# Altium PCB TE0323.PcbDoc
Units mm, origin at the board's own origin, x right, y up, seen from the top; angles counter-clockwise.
Board outline 115 x 70 mm, 4 copper layers (L 01 (Top), L 02, L 03, L 04 (Bot)), stack 1.564 mm thick; 54 components, 144 nets, 448 pads, 152 vias.
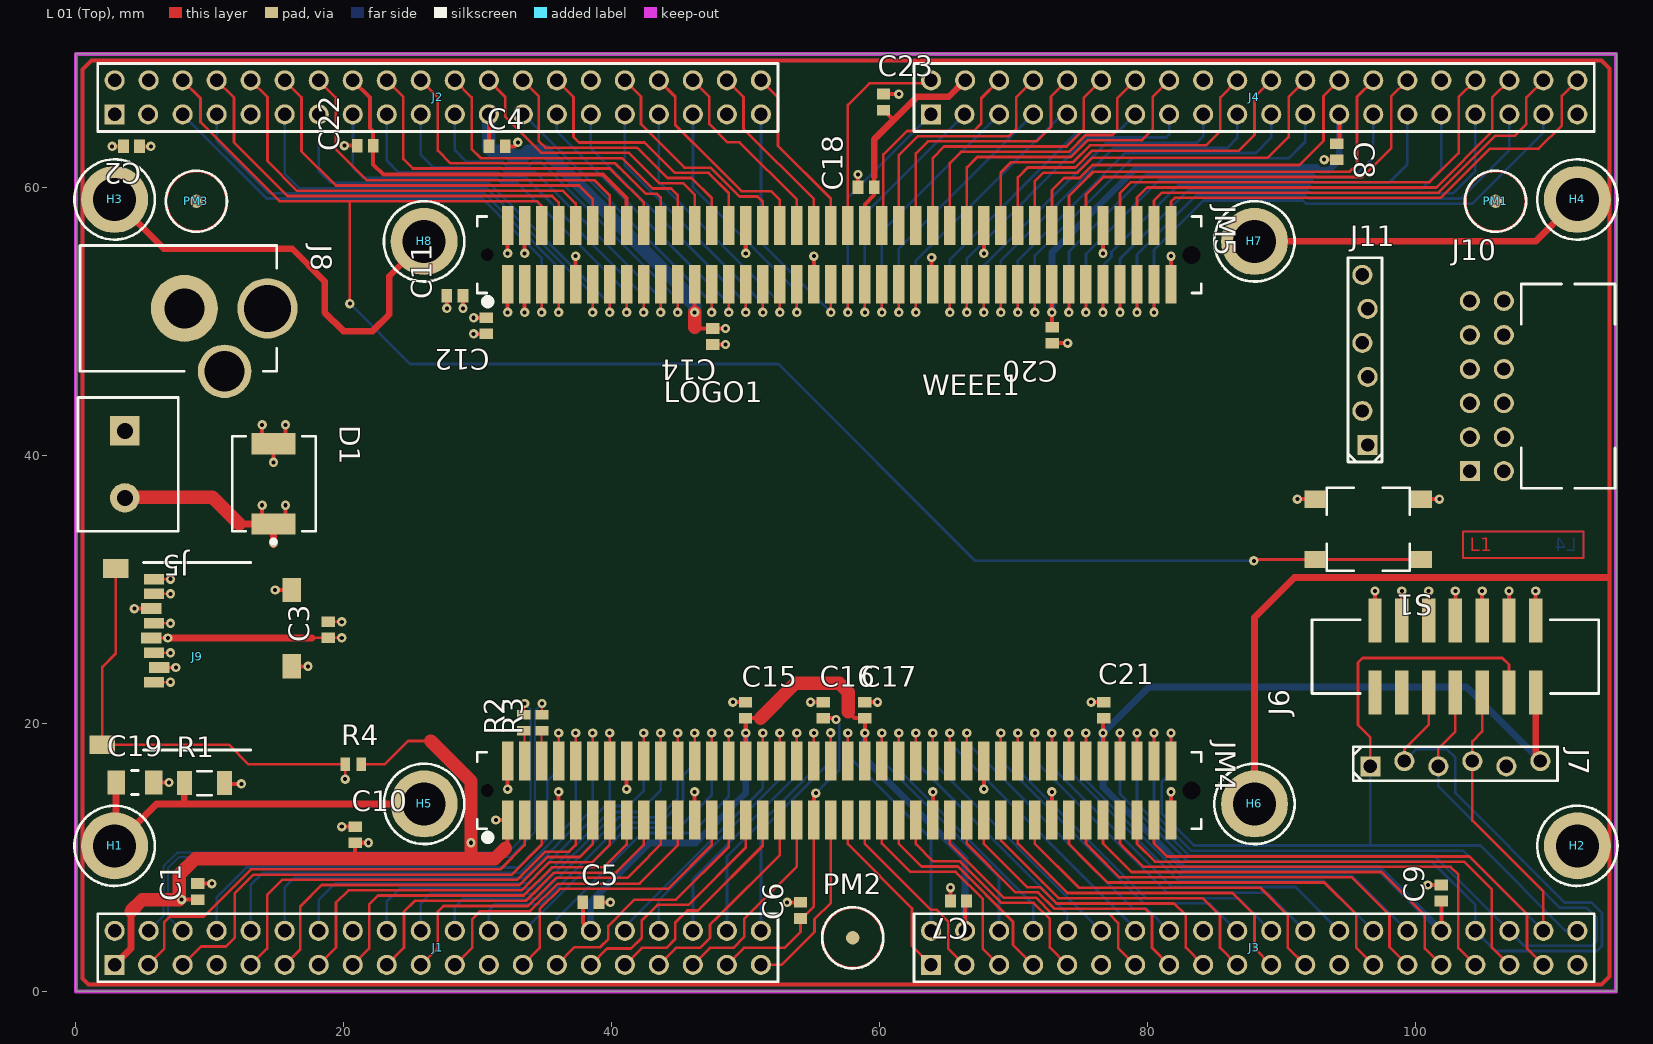
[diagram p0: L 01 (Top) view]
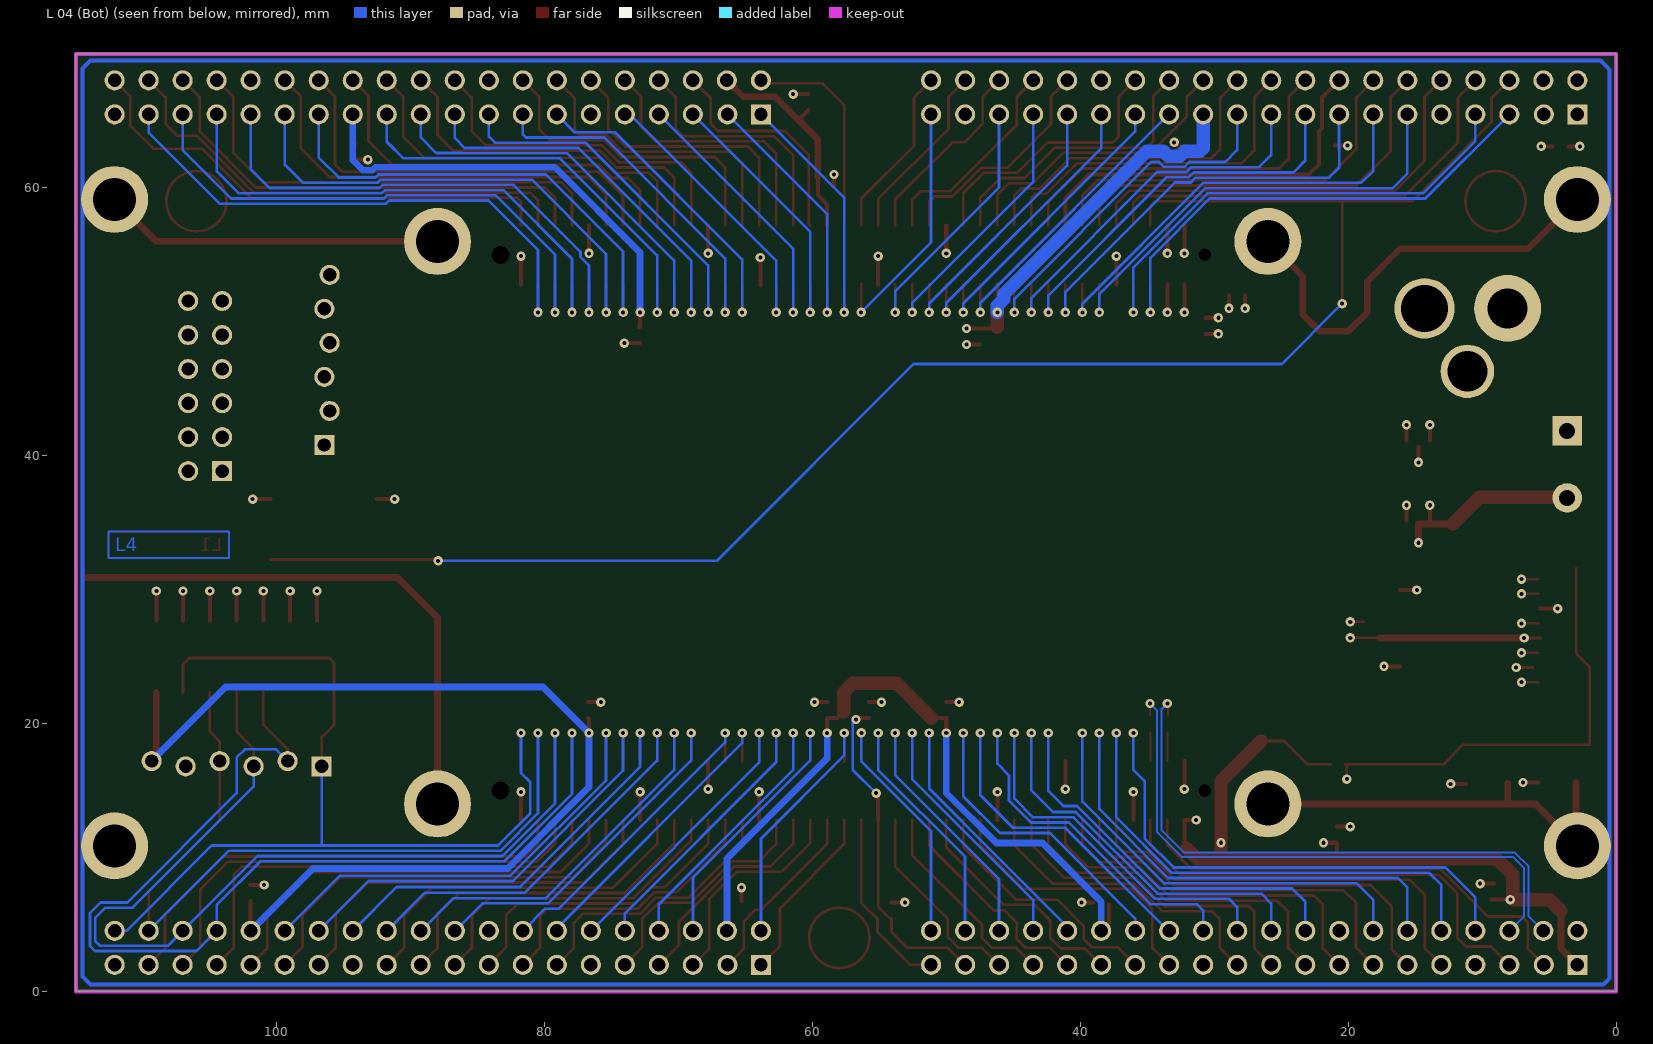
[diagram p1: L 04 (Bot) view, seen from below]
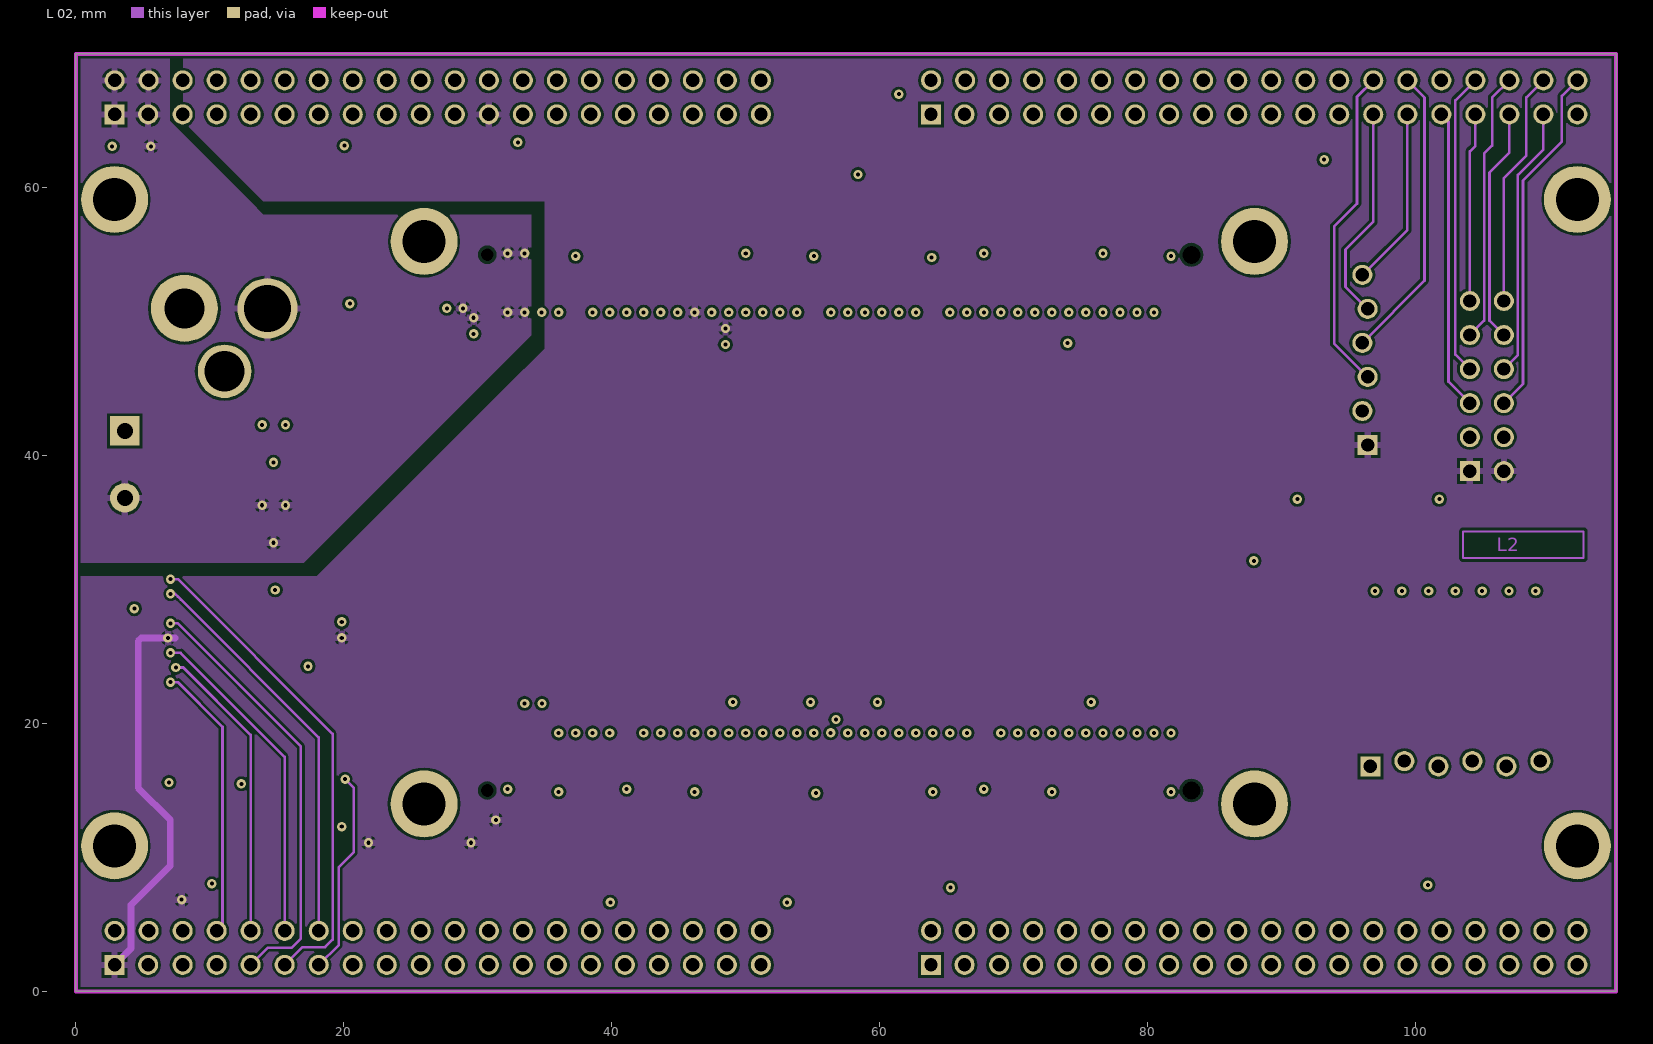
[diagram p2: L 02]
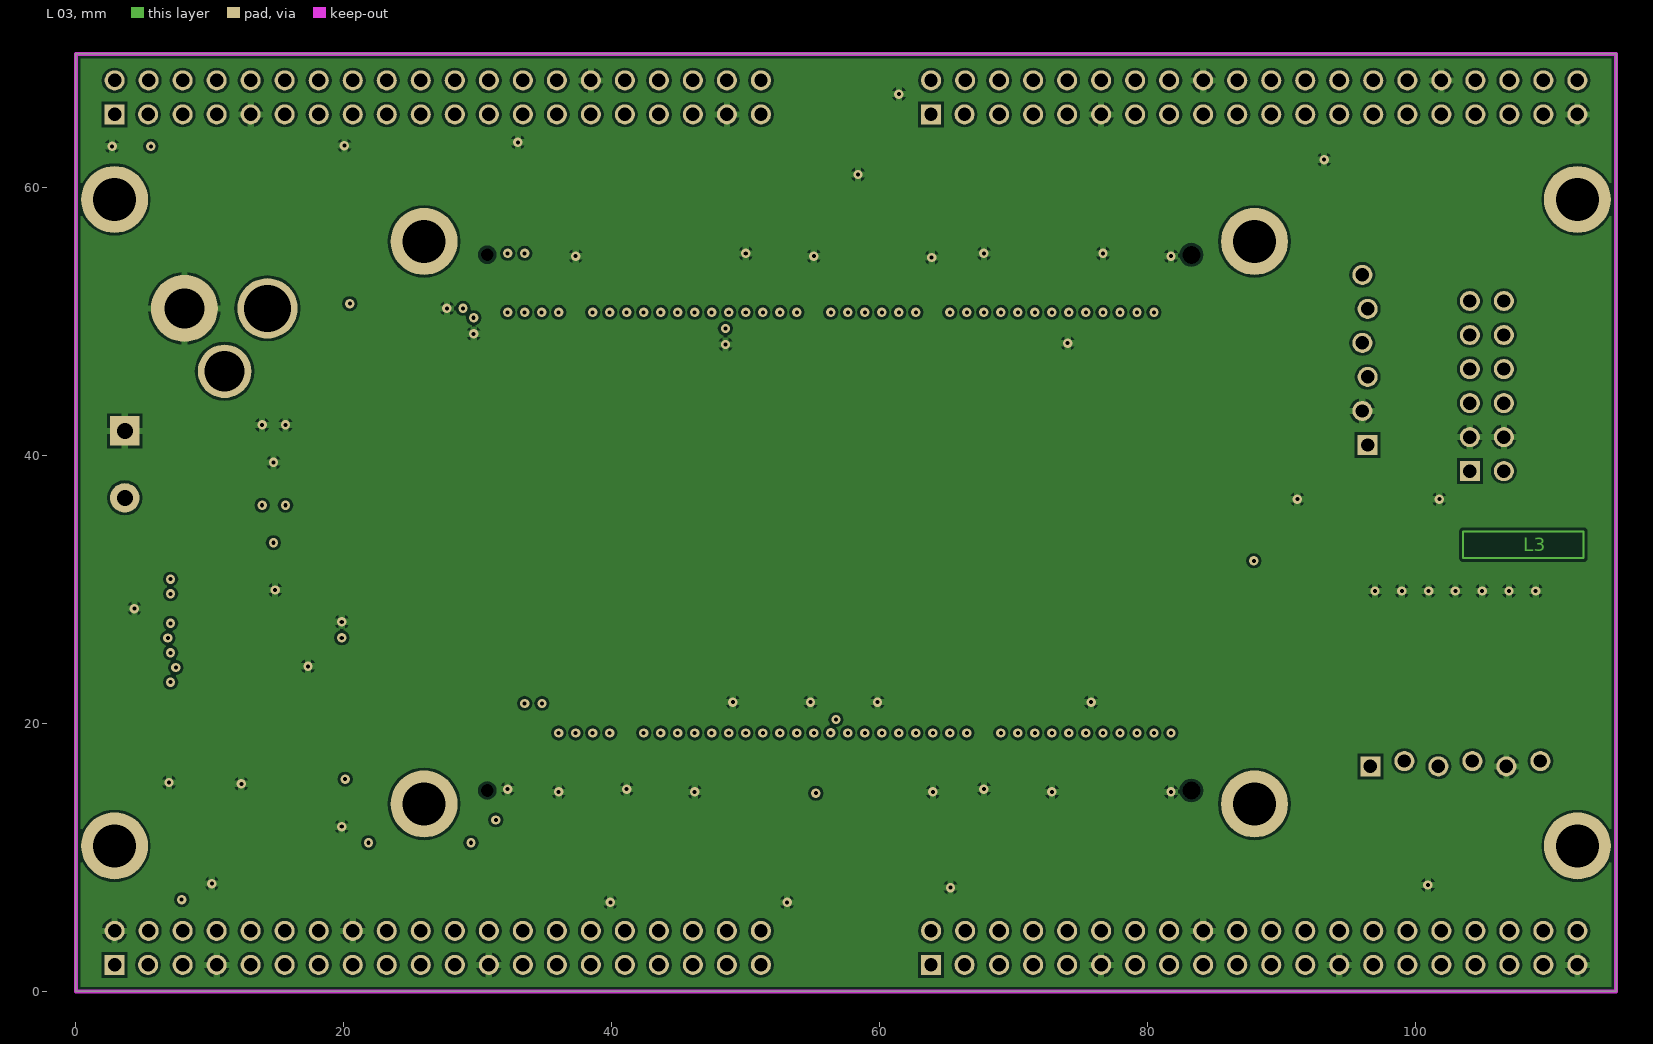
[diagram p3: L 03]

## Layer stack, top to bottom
L 01 (Top): signal copper 0.05
Dielectric: core 0.134, FR-4, Dk 4.8
L 02: signal copper 0.033
Dielectric: prepreg 1.13, FR-4, Dk 4.8
L 03: signal copper 0.033
Dielectric: core 0.134, FR-4, Dk 4.8
L 04 (Bot): signal copper 0.05

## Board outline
0,0 0,70 115,70 115,0

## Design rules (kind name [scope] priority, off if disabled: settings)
Clearance Clearance_Polygon [(InPolygon)] p1: gap=0.2
Clearance [All] p2: gap=0.19
ComponentClearance ComponentClearance_WEEE [(InComponent('WEEE'))] p1: gap=-20 collisioncheckmode=3 verticalgap=0.254 showdistances=FALSE
ComponentClearance ComponentClearance_LOGO [(InComponent('LOGO1'))] p2: gap=-30 collisioncheckmode=3 verticalgap=0.254 showdistances=FALSE
ComponentClearance [All] p3: gap=-0.05 collisioncheckmode=3 verticalgap=0.254 showdistances=FALSE
DiffPairsRouting [All] p1: maxlimit=1 minlimit=0.189 mostfreqgap=1 toplayer_maxgap=0.191 toplayer_prefgap=0.19 midlayer1_mingap=1 midlayer2_mingap=1 bottomlayer_maxgap=0.191 bottomlayer_prefgap=0.19 maxuncoupledlength=12.7
FabricationTestPointUsage TestPointUsage [All] p1: valid=0 allowmultiple=FALSE
FabricationTestpoint Testpoint [All] p1: side=3 testpointundercomponent=TRUE minsize=1.016 maxsize=2.54 preferedsize=1.524 minholesize=0 maxholesize=1.016 preferedholesize=0.813 testpointgrid=0.025 allowsidetop=TRUE allowsidebottom=TRUE usegrid=TRUE gridtolerance=0
HoleSize [All] p1: absolutevalues=TRUE maxlimit=5 minlimit=0.3 maxpercent=80.000 minpercent=20.000
MinimumAnnularRing [Not(InComponent('J7'))] p1: minimumring=0.2
PolygonConnect [All] p1: connectstyle=Relief reliefconductorwidth=0.5 reliefentries=4 polygonreliefangle="90 Angle"
RoutingLayers [All] p1: top layer_v5=TRUE mid layer 1_v5=FALSE mid layer 2_v5=FALSE bottom layer_v5=TRUE
RoutingVias [All] p1: holewidth=0.3 width=0.8 viastyle="Through Hole" minholewidth=0.3 minwidth=0.7 maxholewidth=1 maxwidth=3
SilkscreenOverComponentPads [All] p1: minsilkscreentomaskgap=0.254
SolderMaskExpansion SolderMaskExpansion_VIA [(IsVia)] p1: expansion=-10
SolderMaskExpansion [All] p2: expansion=0.102
Width Width_logo [InComponent(LOGO1)] p1: maxlimit=0.254 minlimit=0.004 preferedwidth=0.254
Width Width_100Ohm [(InNetClass('I100'))] p2: maxlimit=0.15 minlimit=0.15 preferedwidth=0.15
Width [All] p3: maxlimit=3 minlimit=0.15 preferedwidth=0.2
21 further rules are at their usual default settings.

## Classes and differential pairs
component class Main: H1 H2 H3 H4 H5 H6 H7 H8 LOGO1 PM1 PM2 PM3 WEEE1
component class Connector: C1 C2 C3 C4 C5 C6 C7 C8 C9 C22 C23 J1 J2 J3 J4 J9 J10 J11 R4
component class Signals: C10 C11 C12 C14 C15 C16 C17 C18 C19 C20 C21 D1 J5 J6 J7 J8 JM4 JM5 R1 R2 R3 S1
net class I100: B2B_D_N B2B_D_P B2BR_D_N B2BR_D_P
differential pair B2B_D: +B2B_D_P -B2B_D_N
differential pair B2BR_D: +B2BR_D_P -B2BR_D_N

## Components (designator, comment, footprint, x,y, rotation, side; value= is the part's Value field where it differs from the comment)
C1 "100nF" CAPC1608N 9.1,7.45 r90 top
C2 "100nF" CAPC1608N 4.15,63.1 r180 top
C3 "100nF" CAPC1608N 18.85,27 r90 top
C4 "100nF" CAPC1608N 31.45,63.1 r0 top
C5 "100nF" CAPC1608N 38.45,6.65 r0 top
C6 "100nF" CAPC1608N 54.1,6.05 r90 top
C7 "100nF" CAPC1608N 65.9,6.75 r180 top
C8 "100nF" CAPC1608N 94.15,62.7 r270 top
C9 "100nF" CAPC1608N 101.95,7.35 r90 top
C10 "100nF" CAPC1608N 20.85,11.7 r90 top
C11 "100nF" CAPC1608N 28.3,51.95 r180 top
C12 "100nF" CAPC1608N 30.65,49.7 r270 top
C14 "100nF" CAPC1608N 47.55,48.9 r270 top
C15 "100nF" CAPC1608N 50,21 r90 top
C16 "100nF" CAPC1608N 55.8,21 r90 top
C17 "100nF" CAPC1608N 58.9,21 r90 top
C18 "100nF" CAPC1608N 59,60.05 r180 top
C19 "100pF" CAPC3216N 4.4,15.6 r0 top
C20 "100nF" CAPC1608N 72.9,49 r270 top
C21 "100nF" CAPC1608N 76.75,21 r90 top
C22 "100nF" CAPC1608N 21.6,63.15 r180 top
C23 "100nF" CAPC1608N 60.3,66.4 r90 top
D1 "MBRS340T3" MBRS340T3 14.75,37.9 r270 top
H1 "MHole3.2mm" MHole3_2mm 2.89,10.87 r0 top locked
H2 "MHole3.2mm" MHole3_2mm 112.11,10.87 r0 top locked
H3 "MHole3.2mm" MHole3_2mm 2.89,59.13 r0 top locked
H4 "MHole3.2mm" MHole3_2mm 112.11,59.13 r0 top locked
H5 "MHole3.2mm" MHole3_2mm 25.999,14.001 r0 top locked
H6 "MHole3.2mm" MHole3_2mm 87.999,14.001 r0 top locked
H7 "MHole3.2mm" MHole3_2mm 87.999,56.001 r0 top locked
H8 "MHole3.2mm" MHole3_2mm 25.999,56.001 r0 top locked
J1 "STIFTLEISTE2.54 OG 2R-40" "STIFTLEISTE2_54 OG 2R-40" 27.02,3.25 r0 top locked
J2 "STIFTLEISTE2.54 OG 2R-40" "STIFTLEISTE2_54 OG 2R-40" 27.02,66.75 r0 top locked
J3 "STIFTLEISTE2.54 OG 2R-40" "STIFTLEISTE2_54 OG 2R-40" 87.98,3.25 r0 top locked
J4 "STIFTLEISTE2.54 OG 2R-40" "STIFTLEISTE2_54 OG 2R-40" 87.98,66.75 r0 top locked
J5 "ARK500-2" ARK500-2 3.65,39.35 r270 top
J6 "WANNE2mm2R-14" WANNE2mm2R-14 103,25 r180 top
J7 "Stiftleiste versetzt 1-reihig, 6pol." "STIFTLEISTE2_54 OG 1R-6V" 103,17 r0 top
J8 "2.1mm Jack" WS-DC001 14.3,51 r0 top
J9 "Micro SD Socket" 112A-TXAR-R01 9.05,25 r90 top locked
J10 "BUCHSENLEISTE-2.54-12-2R-90" BUCHSENLEISTE-2.54-12-2R-90 105.35,45.2 r90 top locked
J11 "Stiftleiste versetzt 1-reihig, 6pol." "STIFTLEISTE2_54 OG 1R-6V" 96.25,47.15 r90 top locked
JM4 "Steckerleiste 1,27mm 80Pol. SMD" 6110-080-00-10 57,15 r0 top locked
JM5 "Steckerleiste 1,27mm 80Pol. SMD" 6110-080-00-10 57,55 r0 top locked
LOGO1 "LOGO 5" "Logo 5" 50.75,38.4 r0 top
PM1 "FIDU-DOT" FIDU-DOT 106,59 r0 top
PM2 "FIDU-DOT" FIDU-DOT 58,4 r0 top
PM3 "FIDU-DOT" FIDU-DOT 9,59 r0 top locked
R1 "1M" RESC3216N 9.6,15.55 r0 top
R2 "0R" RESC1609N 33.45,20.05 r90 top
R3 "0R" RESC1609N 34.8,20.05 r90 top
R4 "3K3" RESC1609N 20.7,16.95 r0 top
S1 "SW PB DTSM61N" DTSM61N 96.5,34.5 r180 top
WEEE1 "WEEE 5" WEEE5_10_25mm 66.9,39.65 r0 top

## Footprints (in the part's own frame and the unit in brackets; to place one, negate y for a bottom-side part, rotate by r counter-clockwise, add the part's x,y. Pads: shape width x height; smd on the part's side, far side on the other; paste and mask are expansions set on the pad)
112A-TXAR-R01 [mm] "Micro SD Socket"
  rect 0.8x1.5 smd: 1(-1.915,3.225) 2(-0.815,2.825) 3(0.285,3.225) 4(1.385,3.425) 5(2.485,3.225) 6(3.585,3.425) 7(4.685,3.225) 8(5.785,3.225)
  rect 1.4x1.9 smd: 9(-6.575,7.075) 9(6.575,6.075)
  rect 1.8x1.4 smd: 10(-0.725,-7.075) 10(4.975,-7.075)
  silkscreen extent -6.97,-4 7.03,4, body extent -8.02,-8.77 8.02,13, height 1.83
6110-080-00-10 [mm]
  rect 0.85x2.9 smd: 1(-24.765,-2.2) 2(-24.765,2.2) 3(-23.495,-2.2) 4(-23.495,2.2) 5(-22.225,-2.2) 6(-22.225,2.2) 7(-20.955,-2.2) 8(-20.955,2.2) 9(-19.685,-2.2) 10(-19.685,2.2) 11(-18.415,-2.2) 12(-18.415,2.2) 13(-17.145,-2.2) 14(-17.145,2.2) 15(-15.875,-2.2) 16(-15.875,2.2) 17(-14.605,-2.2) 18(-14.605,2.2) 19(-13.335,-2.2) 20(-13.335,2.2) 21(-12.065,-2.2) 22(-12.065,2.2) 23(-10.795,-2.2) 24(-10.795,2.2) 25(-9.525,-2.2) 26(-9.525,2.2) 27(-8.255,-2.2) 28(-8.255,2.2) 29(-6.985,-2.2) 30(-6.985,2.2) 31(-5.715,-2.2) 32(-5.715,2.2) 33(-4.445,-2.2) 34(-4.445,2.2) 35(-3.175,-2.2) 36(-3.175,2.2) 37(-1.905,-2.2) 38(-1.905,2.2) 39(-0.635,-2.2) 40(-0.635,2.2) 41(0.635,-2.2) 42(0.635,2.2) 43(1.905,-2.2) 44(1.905,2.2) 45(3.175,-2.2) 46(3.175,2.2) 47(4.445,-2.2) 48(4.445,2.2) 49(5.715,-2.2) 50(5.715,2.2) 51(6.985,-2.2) 52(6.985,2.2) 53(8.255,-2.2) 54(8.255,2.2) 55(9.525,-2.2) 56(9.525,2.2) 57(10.795,-2.2) 58(10.795,2.2) 59(12.065,-2.2) 60(12.065,2.2) 61(13.335,-2.2) 62(13.335,2.2) 63(14.605,-2.2) 64(14.605,2.2) 65(15.875,-2.2) 66(15.875,2.2) 67(17.145,-2.2) 68(17.145,2.2) 69(18.415,-2.2) 70(18.415,2.2) 71(19.685,-2.2) 72(19.685,2.2) 73(20.955,-2.2) 74(20.955,2.2) 75(22.225,-2.2) 76(22.225,2.2) 77(23.495,-2.2) 78(23.495,2.2) 79(24.765,-2.2) 80(24.765,2.2)
  round 0 hole 0.95 unplated: H1(-26.29,0)
  round 0 hole 1.35 unplated: H2(26.29,0)
  silkscreen extent -27.03,-3.75 27.03,2.86, body extent -27.03,-2.86 27.03,2.86, height 5.61
ARK500-2 [mm] "AR-Klemmen 250V 2pol. grau"
  rect 2.2x2.2 hole 1.2: 1(-2.5,0)
  round 2.2 hole 1.2: 2(2.5,0)
  silkscreen extent -5,-3.5 5,4, body extent -6.6,-4.5 6,5, height 10
BUCHSENLEISTE-2.54-12-2R-90 [mm]
  rect 1.5x1.5 hole 1: 1(-6.35,1.27)
  round 1.5 hole 1: 2(-6.35,-1.27) 3(-3.81,1.27) 4(-3.81,-1.27) 5(-1.27,1.27) 6(-1.27,-1.27) 7(1.27,1.27) 8(1.27,-1.27) 9(3.81,1.27) 10(3.81,-1.27) 11(6.35,1.27) 12(6.35,-1.27)
  silkscreen extent -7.62,-9.57 7.62,-2.57
CAPC1608N [mm] "Vishay VJ0603 1.6 x 0.8 (+0.15/-0.1) 0.4 +/- 0,15mm Kontakte"
  rect 0.8x1 smd: 1(-0.6,0) 2(0.6,0)
  body extent -1.15,-0.65 1.15,0.65, height 0.95
CAPC3216N [mm] "Vishay VJ1206 3.2 x 1.6 (+/- 0.15), 0.4mm - 0.8mm Kontakte"
  rect 1.3x1.8 smd: 1(-1.4,0) 2(1.4,0)
  silkscreen extent -0.25,-0.9 0.25,0.9, body extent -2.3,-1.15 2.3,1.15, height 1.8
DTSM61N [mm] "SMD-Taster"
  rect 1.55x1.3 smd: 1(-3.975,2.25) 1(3.975,2.25) 2(-3.975,-2.25) 2(3.975,-2.25)
  silkscreen extent -3.1,-3.1 3.1,3.1, body extent -5,-4.1 5,4.1, height 4.5
FIDU-DOT [mm]
  round 1 smd paste-1 mask+2: 0(0,0)
  L 01 (Top) circle w0.2: c0,0 r2.25
  silkscreen extent -2.28,-2.29 2.29,2.29
"Logo 5" [mm]
MBRS340T3 [mm]
  rect 1.6x3.27 smd: 1(3,0) 2(-3,0)
  silkscreen extent -3.56,-3.07 4.45,3.15, body extent -4.56,-4.07 4.55,4.15, height 2.6
MHole3_2mm [mm]
  round 5 hole 3.2: 1(0,0)
  silkscreen extent -3,-3 3,3
RESC1609N [mm] "Vishay D0603 1.55 x 0.85 (+0.1/-0.05) 0.3 +/- 0,2mm Kontakte"
  rect 0.7x1 smd: 1(-0.6,0) 2(0.6,0)
  body extent -1.1,-0.65 1.1,0.65, height 0.5
RESC3216N [mm] "Vishay D1206 3.2 x 1.6 (+/- 0.15), 0.2mm - 0.6mm Kontakte"
  rect 1.1x1.8 smd: 1(-1.5,0) 2(1.5,0)
  silkscreen extent -0.55,-0.9 0.55,0.9, body extent -2.3,-1.15 2.3,1.15, height 0.6
"STIFTLEISTE2_54 OG 1R-6V" [mm]
  rect 1.5x1.5 hole 1: 1(-6.35,-0.2)
  round 1.5 hole 1: 2(-3.81,0.2) 3(-1.27,-0.2) 4(1.27,0.2) 5(3.81,-0.2) 6(6.35,0.2)
  silkscreen extent -7.62,-1.27 7.62,1.27, body extent -7.6,-1.25 7.6,1.25, height 9
"STIFTLEISTE2_54 OG 2R-40" [mm]
  rect 1.5x1.5 hole 1: 1(-24.13,-1.27)
  round 1.5 hole 1: 2(-24.13,1.27) 3(-21.63,-1.27) 4(-21.59,1.27) 5(-19.05,-1.27) 6(-19.05,1.27) 7(-16.51,-1.27) 8(-16.51,1.27) 9(-13.97,-1.27) 10(-13.97,1.27) 11(-11.43,-1.27) 12(-11.43,1.27) 13(-8.89,-1.27) 14(-8.89,1.27) 15(-6.35,-1.27) 16(-6.35,1.27) 17(-3.81,-1.27) 18(-3.81,1.27) 19(-1.27,-1.27) 20(-1.27,1.27) 21(1.27,-1.27) 22(1.27,1.27) 23(3.81,-1.27) 24(3.81,1.27) 25(6.35,-1.27) 26(6.35,1.27) 27(8.89,-1.27) 28(8.89,1.27) 29(11.43,-1.27) 30(11.43,1.27) 31(13.97,-1.27) 32(13.97,1.27) 33(16.51,-1.27) 34(16.51,1.27) 35(19.05,-1.27) 36(19.05,1.27) 37(21.59,-1.27) 38(21.59,1.27) 39(24.13,-1.27) 40(24.13,1.27)
  silkscreen extent -25.4,-2.54 25.4,2.54, body extent -26.4,-3.54 26.4,3.54, height 11.3
WANNE2mm2R-14 [mm]
  rect 1x3.3 smd: 1(-6,-2.685) 2(-6,2.685) 3(-4,-2.685) 4(-4,2.685) 5(-2,-2.685) 6(-2,2.685) 7(0,-2.685) 8(0,2.685) 9(2,-2.685) 10(2,2.685) 11(4,-2.685) 12(4,2.685) 13(6,-2.685) 14(6,2.685)
  silkscreen extent -10.7,-2.75 10.7,2.75, body extent -11.6,-4.6 11.6,4.6, height 6.5
WEEE5_10_25mm [mm]
WS-DC001 [mm]
  round 4.5 hole 3.5: 1(0,0)
  round 4 hole 3: 2(-3.2,-4.7)
  round 5 hole 3: 3(-6.2,0)
  silkscreen extent -14,-4.7 0.7,4.7, body extent -14.25,-6.95 2.5,5, height 11.3

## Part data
C1 C2 C3 C4 C5 C6 C7 C8 C9 C10 C11 C12 C14 C15 C16 C17 C18 C20 C21 C22 C23: library part 21382, "KON 100nF 50V X7R SMD"
C19: library part 22679, "KON 100pF X7R"
D1: library part 22887, "MBRS340T3 SMD"
H1 H2 H3 H4 H5 H6 H7 H8: library part 22898
J1 J2 J3 J4: library part 22320, "Stiftleiste gerade 2-reihig, 40pol"
J5: library part 20123, "Schraubklemme LP 2 pol ARK500-2"
J6: library part 22744, "Stiftleiste Wanne 14polig SMD"
J7 J11: library part 22911
J8: library part 22832, "STE 2,1mm Buchse"
J9: library part 23193
J10: library part 23185, "Buchsenleiste 2-reihig, 12pol 90°"
JM4 JM5: library part 23749, "STE B2B 80Pol. Steckerleiste 1,27mm SMD"
LOGO1: library part 22903
PM1 PM2 PM3: library part 22906
R1: library part 22757, "WID SMD 1M"
R2 R3: library part 21491, "WID SMD 0R"
R4: library part 22433, "WID SMD 3K3 1% 0,1W"
S1: library part 22596, "Taster Miniatur Leiterplatte 1.6N"
WEEE1: library part 23537, "WEEE 5 (10.25mm)"

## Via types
v1: diameter 0.7, hole 0.3, L 01 (Top) to L 04 (Bot), 152 vias

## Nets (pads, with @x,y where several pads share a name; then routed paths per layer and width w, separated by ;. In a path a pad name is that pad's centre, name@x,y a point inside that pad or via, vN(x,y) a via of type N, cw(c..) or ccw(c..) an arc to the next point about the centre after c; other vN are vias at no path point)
1.2V: C18.1 C23.1 J4.4 JM5.44 | length 16.4
  L 01 (Top) w0.3: JM5.44 58.905,58.755 59.6,59.45 C18.1 59.6,60.85 ; C23.1 61.05,65.05
  L 01 (Top) w0.5: 59.6,60.85 59.6,63.6 62.8,66.8 65.17,66.8 J4.4
2.5V: C8.1 C20.1 J4.25 JM5.65 | length 37.8
  L 01 (Top) w0.3: JM5.65 v1(72.875,50.705) 72.875,49.625 C20.1 ; C8.1 94.33,63.48 J4.25
  L 04 (Bot) w0.5: v1(72.875,50.705) 72.875,55.175 79.24,61.54 92.643,61.54 92.873,61.31 93.56,61.31 94.33,62.08 J4.25
3.3V: C1.1 C3.1 C4.1 C10.1 C14.1 J1.1 J2.23 J9.4 J10.1 J10.2 J11.1 JM4.1 JM5.23 R4.2 | length 135.6
  L 01 (Top) w0.2: J9.4 v1(6.865,26.385) ; 17.635,26.385 17.65,26.4 C3.1 v1(19.85,26.4) ; R4.2 23.05,16.95 24.8,18.7 26.5,18.7 ; 46.205,51.233 JM5.23
  L 01 (Top) w0.3: v1@7.725,6.85 v1(7.9,6.85) C1.1 C1.1@9.3,6.85 ; 20.85,9.95 C10.1 v1(21.85,11.1) ; J2.23 30.83,63.12 C4.1 ; v1(31.35,12.8) JM4.1 32.235,10.86 32.075,10.7 ; 46.205,49.6 46.305,49.5 C14.1 v1(48.5,49.5) ; v1(46.205,50.705) JM5.23
  L 01 (Top) w0.5: J1.1 4.11,3.2 4.11,6 ; v1(6.865,26.385) 17.635,26.385
  L 01 (Top) w1: 4.11,6 4.96,6.85 7.725,6.85 7.725,8.725 8.9,9.9 29.4,9.9 ; 26.5,18.7 29.5,15.7 v1(29.5,11.1) 29.5,10 29.4,9.9 ; 32.075,10.7 31.275,9.9 29.4,9.9 ; 46.205,49.6 v1(46.205,50.705)
  L 02 w0.5: J1.1 4.11,3.2 4.11,6.46 7.05,9.4 7.05,12.8 4.65,15.2 4.65,26.15 4.885,26.385 7.415,26.385
  L 04 (Bot) w1: J2.23 30.83,62.97 31.08,62.72 32.209,62.72 32.569,62.36 33.431,62.36 33.791,62.72 35.047,62.72 45.725,52.042 45.725,51.689 46.205,51.209 v1(46.205,50.705)
5V: C22.1 J2.16 JM5.16 | length 28.9
  L 01 (Top) w0.3: J2.16 21.95,66.74 21.95,64.45 22.2,64.2 C22.1 22.2,61.75 22.949,61.001 39.349,61.001 41.125,59.225 JM5.16
5VB2B: C2.1 C11.1 C12.1 D1.1 J2.1 J2.2 J2.3 J2.4 J5.2 J8.1 JM5.1 JM5.2 JM5.3 JM5.4 | length 27.3
  L 01 (Top) w0.3: C2.1 v1(5.6,63.1) ; D1.1@13.9,35.149 v1(13.9,36.299) ; v1(14.75,33.499) D1.1@14.75,34.649 ; D1.1@15.65,35.149 v1(15.65,36.299) ; v1(28.9,51) C11.1 ; v1(29.7,50.3) C12.1 ; v1(32.235,50.705) JM5.1 ; v1(32.235,55.105) JM5.2 ; v1(33.505,50.705) JM5.3 ; v1(33.505,55.105) JM5.4
  L 01 (Top) w0.5: 12.2,34.9 D1.1 v1(14.75,33.499) v1@14.75,33.35
  L 01 (Top) w1: J5.2@4.5,36.9 10.2,36.9 12.2,34.9 ; J2.3@5.36,65.48 5.375,65.465 5.39,65.45 J2.3 ; J2.4@5.39,67.98 J2.4
/MR: J2.6 JM5.6 S1.1 | length 128.8
  L 01 (Top) w0.2: J2.6 9.3,66.69 9.3,64.9 15.199,59.001 34.429,59.001 34.775,58.654 JM5.6 ; v1(20.45,51.35) 20.45,58.901 ; v1(87.95,32.15) 88.05,32.25 92.525,32.25 S1.1@100.475,32.25
  L 04 (Bot) w0.2: v1(20.45,51.35) 24.95,46.85 52.45,46.85 67.15,32.15 v1(87.95,32.15)
/RESET: J2.8 JM5.8 | length 33
  L 01 (Top) w0.2: J2.8 11.8,66.73 11.8,63.4 15.809,59.391 35.559,59.391 36.045,58.905 JM5.8
AWAKE: J2.25 JM5.25 | length 22.7
  L 01 (Top) w0.2: v1(47.475,50.705) JM5.25
  L 04 (Bot) w0.2: J2.25 33.404,65.48 47.475,51.409 v1(47.475,50.705)
B2B_D_N: JM4.6 R3.1 | length 2.2
  L 01 (Top) w0.15: JM4.6 R3.1@34.775,19.35
B2B_D_P: JM4.4 R2.1 | length 2.2
  L 01 (Top) w0.15: JM4.4 R2.1@33.505,19.35
B2B_PROGB: J2.21 JM5.21 | length 27.3
  L 01 (Top) w0.2: v1(44.935,50.705) JM5.21
  L 04 (Bot) w0.2: J2.21 28.29,62.81 29.17,61.93 31.882,61.93 32.242,61.57 33.758,61.57 34.118,61.93 34.72,61.93 44.935,51.715 v1(44.935,50.705)
B2BR_D_N: J1.6 R3.2 | length 44.2
  L 01 (Top) w0.15: R3.2 v1(34.8,21.5)
  L 04 (Bot) w0.15: J1.6 6.87,5.62 6.87,9.2 7.695,10.025 32.381,10.025 34.29,11.934 34.29,20.89 ; 34.29,20.99 v1(34.8,21.5)
B2BR_D_P: J1.4 R2.2 | length 44.2
  L 01 (Top) w0.15: R2.2 33.45,21.45 v1(33.5,21.5)
  L 04 (Bot) w0.15: J1.4 6.53,5.62 6.53,9.341 7.554,10.365 32.24,10.365 33.95,12.075 33.95,20.95 ; v1(33.5,21.5) 33.95,21.05
D1: J2.29 JM5.29 | length 21.7
  L 01 (Top) w0.2: v1(50.015,50.705) JM5.29
  L 04 (Bot) w0.2: J2.29 38.45,62.95 50.015,51.385 v1(50.015,50.705)
D2: J2.31 JM5.31 | length 21.1
  L 01 (Top) w0.2: v1(51.285,50.705) JM5.31
  L 04 (Bot) w0.2: J2.31 40.99,61.66 51.285,51.365 v1(51.285,50.705)
D3: J2.33 JM5.33 | length 20.6
  L 01 (Top) w0.2: v1(52.555,50.705) JM5.33
  L 04 (Bot) w0.2: J2.33 43.53,60.42 52.555,51.395 v1(52.555,50.705)
D4: J2.24 JM5.24 | length 22.1
  L 01 (Top) w0.2: J2.24 32.05,66.8 32.05,65.329 34.769,62.611 41.289,62.611 43.56,60.34 45.36,60.34 46.205,59.495 JM5.24
D5: J2.26 JM5.26 | length 21.7
  L 01 (Top) w0.2: J2.26 34.55,66.84 34.55,63.5 35.049,63.001 41.899,63.001 44.17,60.73 45.97,60.73 47.475,59.225 JM5.26
D6: J2.28 JM5.28 | length 20.5
  L 01 (Top) w0.2: J2.28 37.15,66.78 37.15,63.8 37.56,63.391 42.46,63.391 44.73,61.12 47.23,61.12 48.745,59.605 JM5.28
D7: J2.32 JM5.32 | length 17
  L 01 (Top) w0.2: J2.32 42.2,66.81 42.2,64.75 45.44,61.51 47.392,61.51 49.552,59.35 50.901,59.35 51.285,58.966 JM5.32
DONE: J2.10 JM5.10 | length 32.5
  L 01 (Top) w0.2: J2.10 14.3,66.77 14.3,62 16.519,59.781 34.2,59.781 36.37,59.781 37.315,58.836 JM5.10
DOUT: J2.11 JM5.11 | length 34.6
  L 01 (Top) w0.2: v1(38.585,50.705) JM5.11
  L 04 (Bot) w0.2: J2.11 15.59,61.06 16.67,59.98 30.668,59.98 38.585,52.063 v1(38.585,50.705)
FGND: C19.1 H1.1 H2.1 H3.1 H4.1 H5.1 H6.1 H7.1 H8.1 R1.1 | length 859.7
  L 01 (Top) w0.3: 0.5,0.95 0.95,0.5 113.9,0.5 114.5,1.1 114.5,10.87 114.5,53.45 114.5,59.13 114.5,68.9 113.9,69.5 1.175,69.5 0.5,68.825 0.5,59.13 0.5,56.65 0.5,10.87 0.5,0.95
  L 01 (Top) w0.5: H1.1 6.021,14.001 8.1,14.001 ; H3.1 6.57,55.45 16.15,55.45 18.575,53.025 18.575,50.7 19.975,49.3 22.15,49.3 23.4,50.55 23.4,53.401 H8.1 ; H1.1@3,11 C19.1 ; R1.1 8.1,14.001 ; H5.1 8.1,14.001 ; H6.1 87.999,27.924 90.975,30.9 114.335,30.9 ; H7.1 108.981,56.001 H4.1
  L 04 (Bot) w0.3: 0.5,0.95 0.95,0.5 113.9,0.5 114.5,1.1 114.5,10.87 114.5,57.65 114.5,59.13 114.5,68.9 113.9,69.5 1.175,69.5 0.5,68.825 0.5,59.13 0.5,57.85 0.5,10.87 0.5,0.95
GND: C1.2 C2.2 C3.2 C4.2 C5.2 C6.2 C7.2 C8.2 C9.2 C10.2 C11.2 C12.2 C14.2 C15.2 C16.2 C17.2 C18.2 C19.2 C20.2 C21.2 C22.2 C23.2 D1.2 J1.2 J1.7 J1.16 J1.23 J2.9 J2.30 J2.37 J3.11 J3.18 J3.25 J3.39 J4.11 J4.18 J4.32 J4.39 J5.1 J6.1 J6.3 J6.5 J6.7 J6.9 J6.11 J6.13 J7.5 J8.3 J9.6 J9.10 J10.3 J10.4 J11.2 JM4.2 JM4.7 JM4.16 JM4.23 JM4.51 JM4.58 JM4.65 JM4.79 JM5.9 JM5.30 JM5.37 JM5.51 JM5.58 JM5.72 JM5.79 R1.2 S1.2 | length 79.8
  L 01 (Top) w0.2: C3.2 v1(19.85,27.6)
  L 01 (Top) w0.3: v1(2.7,63.1) C2.2 ; v1(4.365,28.585) J9.6 ; C19.2 v1(6.95,15.6) ; C1.2 v1(10.15,8.05) ; R1.2@11.2,15.5 v1(12.35,15.5) ; D1.2@13.9,41.15 v1(13.9,42.3) ; v1(14.75,39.5) D1.2@14.75,40.65 ; v1(14.875,29.975) J9.10@16.125,29.975 ; D1.2@15.65,41.15 v1(15.65,42.3) ; J9.10@16.125,24.275 v1(17.325,24.275) ; v1(19.85,12.3) C10.2 ; v1(20.05,63.15) C22.2 ; v1(27.7,51) C11.2 ; v1(29.7,49.1) C12.2 ; C4.2 32.75,63.1 32.9,63.25 33,63.25 v1(33,63.4) ; v1(32.235,15.105) JM4.2 ; JM4.7 v1(36.045,14.895) ; JM5.9 v1(37.315,54.895) ; C5.2 v1(39.9,6.65) ; v1(41.125,15.105) JM4.16 ; JM4.23 v1(46.205,14.895) ; C14.2 v1(48.5,48.3) ; v1(49.05,21.6) C15.2 ; v1(50.015,55.105) JM5.30 ; v1(53.1,6.65) C6.2 ; v1(54.85,21.6) C16.2 ; JM5.37 v1(55.095,54.895) ; C18.2 v1(58.4,61) ; C17.2 v1(59.85,21.6) ; C23.2 v1(61.45,67) ; JM5.51@63.9,52.7 63.9,52.8 v1(63.9,54.795) ; JM4.51 v1(63.985,14.895) ; C7.2 v1(65.3,7.75) ; v1(67.795,15.105) JM4.58 ; v1(67.795,55.105) JM5.58 ; JM4.65 v1(72.875,14.895) ; C20.2 v1(74.05,48.4) ; v1(75.8,21.6) C21.2 ; v1(76.685,55.105) JM5.72 ; JM4.79 v1(81.765,14.895) ; JM5.79 v1(81.765,54.895) ; v1(91.2,36.75) S1.2@92.525,36.75 ; v1(93.2,62.1) C8.2 ; J6.13 v1(97,29.9) ; J6.11 v1(99,29.9) ; S1.2@100.475,36.75 v1(101.8,36.75) ; v1(100.95,7.95) C9.2 ; J6.9 v1(101,29.9) ; J6.7 v1(103,29.9) ; J6.5 v1(105,29.9) ; J6.3 v1(107,29.9) ; J6.1 v1(109,29.9)
INIT_B: J2.14 JM5.14 | length 29.8
  L 01 (Top) w0.2: J2.14 19.4,66.75 19.4,62.895 21.734,60.561 38.739,60.561 39.855,59.445 JM5.14
J4-IO01: J1.3 JM4.3 | length 34.9
  L 01 (Top) w0.2: J1.3 6.6,3.19 6.6,5.19 7.01,5.6 9.557,5.6 13.067,9.11 31.685,9.11 33.505,10.93 JM4.3
J4-IO02: J1.5 JM4.5 | length 34.3
  L 01 (Top) w0.2: J1.5 9.34,3.35 11.2,3.35 11.85,4 11.85,7.31 13.26,8.72 32.545,8.72 34.775,10.95 JM4.5
J4-IO03: J1.9 J9.5 JM4.9 | length 65.9
  L 01 (Top) w0.2: J9.5 v1(7.065,27.485) ; J1.9 14.275,3.205 14.275,7.2 15.405,8.33 32.952,8.33 35.052,10.43 36.83,10.43 37.315,10.915 JM4.9
  L 02 w0.2: v1(7.065,27.485) 7.615,27.485 16.8,18.3 16.8,3.95 16.1,3.25 14.32,3.25 J1.9
J4-IO04: J1.11 J9.8 JM4.11 | length 68.3
  L 01 (Top) w0.2: J9.8 v1(7.065,30.785) ; J1.11 16.75,3.14 16.75,6.35 18.34,7.94 33.113,7.94 35.213,10.04 37.64,10.04 38.585,10.985 JM4.11
  L 02 w0.2: v1(7.065,30.785) 7.615,30.785 19.17,19.23 19.17,3.87 18.6,3.3 16.91,3.3 J1.11
J4-IO05: J1.13 J9.9 JM4.13 R4.1 | length 78
  L 01 (Top) w0.2: J9.9@2.975,31.575 2.975,25.225 1.975,24.225 1.975,18.425 11.425,18.425 12.9,16.95 R4.1@20.199,16.95 ; J1.13 19.425,3.275 19.425,6.625 20.35,7.55 33.275,7.55 35.375,9.65 38.575,9.65 39.855,10.93 JM4.13 ; v1(20.1,15.85) R4.1
  L 02 w0.2: J1.13 19.63,3.48 19.63,9.28 20.75,10.4 20.75,15.2 v1(20.1,15.85)
J4-IO06: J1.15 JM4.15 | length 27.9
  L 01 (Top) w0.2: J1.15 21.9,3.21 21.9,6.5 22.56,7.16 33.436,7.16 35.536,9.26 39.41,9.26 41.125,10.975 JM4.15
J4-IO07: J1.17 JM4.17 | length 26.3
  L 01 (Top) w0.2: J1.17 24.5,3.27 24.5,5.96 25.31,6.77 33.598,6.77 35.698,8.87 40.335,8.87 42.395,10.93 JM4.17
J4-IO08: J1.19 JM4.19 | length 25.3
  L 01 (Top) w0.2: J1.19 27.02,3.25 27.02,5.97 27.43,6.38 33.759,6.38 35.859,8.48 39.05,8.48 ; 39.233,8.48 39.05,8.48 ; JM4.19 43.665,10.96 41.927,9.222 41.185,8.48 39.05,8.48
J4-IO09: J1.21 JM4.21 | length 23.5
  L 01 (Top) w0.2: J1.21 29.6,3.29 29.6,5.4 30.19,5.99 33.921,5.99 35.981,8.05 42.075,8.05 44.935,10.91 JM4.21
J4-IO10: J1.25 JM4.25 | length 21.4
  L 01 (Top) w0.2: J1.25 34.625,3.235 34.625,6.143 36.142,7.66 44.21,7.66 47.475,10.925 JM4.25
J4-IO11: J1.27 JM4.27 | length 19.1
  L 01 (Top) w0.2: J1.27 37.23,3.3 39.15,3.3 39.75,3.9 39.75,4.89 41.71,6.85 44.813,6.85 48.745,10.782 JM4.27
J4-IO12: J1.29 JM4.29 | length 18
  L 01 (Top) w0.2: J1.29 39.67,3.2 41.45,3.2 42.25,4 42.25,5.29 43.42,6.46 45.746,6.46 50.015,10.729 JM4.29
J4-IO13: J1.31 JM4.31 | length 16.6
  L 01 (Top) w0.2: J1.31 42.26,3.25 44.1,3.25 44.75,3.9 44.75,5.14 45.65,6.04 46.45,6.04 51.285,10.875 JM4.31
J4-IO14: J1.33 JM4.33 | length 15.7
  L 01 (Top) w0.2: J1.33@43.605,1.98 J1.33 44.8,3.25 46.6,3.25 47.35,4 47.35,4.99 48.01,5.65 52.555,10.195 JM4.33
J4-IO15: J1.35 JM4.35 | length 15.1
  L 01 (Top) w0.2: J1.35 47.34,3.25 49.1,3.25 49.9,4.05 49.9,5.4 50.75,6.25 53.825,9.325 JM4.35
J4-IO16: J1.39 JM4.39 | length 13.9
  L 01 (Top) w0.2: J1.39 52.68,1.98 55.15,4.45 55.15,5.4 56.365,6.615 JM4.39
J4-IO17: J3.1 JM4.41 | length 13.4
  L 01 (Top) w0.2: JM4.41 57.635,10.991 62.425,6.201 62.425,3.405 J3.1
J4-IO18: J3.3 JM4.43 | length 14.2
  L 01 (Top) w0.2: JM4.43 58.905,11.02 63.825,6.1 64.25,6.1 65.125,5.225 65.125,3.205 J3.3
J4-IO19: J3.5 JM4.45 | length 16.4
  L 01 (Top) w0.2: JM4.45 60.175,11.051 62.288,8.938 62.293,8.933 65.688,8.933 67.7,6.921 67.7,3.21 J3.5
J4-IO20: J3.7 JM4.47 | length 16.6
  L 01 (Top) w0.2: JM4.47 61.445,11.021 63.143,9.323 65.85,9.323 69.97,5.202 69.97,3.48 J3.7
J4-IO21: J3.9 JM4.49 | length 18.1
  L 01 (Top) w0.2: JM4.49 62.715,11.011 64.013,9.713 66.011,9.713 69.109,6.615 71.51,6.615 72.725,5.4 72.725,3.265 J3.9
J4-IO22: J3.13 JM4.53 | length 20.5
  L 01 (Top) w0.2: JM4.53 65.255,11.021 69.271,7.005 71.672,7.005 72.887,5.79 77.16,5.79 77.825,5.125 77.825,3.245 J3.13
J4-IO23: J3.15 JM4.55 | length 22
  L 01 (Top) w0.2: JM4.55 66.525,11.026 70.156,7.395 71.833,7.395 73.048,6.18 79.835,6.18 80.35,5.665 80.35,3.26 J3.15
J4-IO24: J3.17 JM4.57 | length 23.3
  L 01 (Top) w0.2: JM4.57 67.795,11.021 71.031,7.785 71.995,7.785 73.21,6.57 81.995,6.57 82.875,5.69 82.875,3.275 J3.17
J4-IO25: J3.19 JM4.59 | length 24.4
  L 01 (Top) w0.2: JM4.59 69.065,11.266 72.156,8.175 73.371,6.96 84.13,6.96 85.425,5.665 85.425,3.265 J3.19
J4-IO26: J3.21 JM4.61 | length 25.9
  L 01 (Top) w0.2: JM4.61 70.335,11.041 72.811,8.565 74.026,7.35 86.365,7.35 88,5.715 88,3.23 J3.21
J4-IO27: J3.23 JM4.63 | length 27.1
  L 01 (Top) w0.2: JM4.63 71.605,11.021 74.886,7.74 88.45,7.74 90.475,5.715 90.475,3.295 J3.23
J4-IO28: J3.27 JM4.67 | length 29.7
  L 01 (Top) w0.2: JM4.67 74.145,11.006 75.476,9.675 77.021,8.13 93.21,8.13 95.6,5.74 95.6,3.25 J3.27
J4-IO29: J3.29 JM4.69 | length 30.9
  L 01 (Top) w0.2: JM4.69 75.415,11.041 76.103,10.352 77.936,8.52 95.27,8.52 98.075,5.715 98.075,3.315 J3.29
J4-IO30: J3.31 JM4.71 | length 32.2
  L 01 (Top) w0.2: JM4.71 76.685,11.041 77.326,10.4 78.816,8.91 97.48,8.91 100.725,5.665 100.725,3.205 J3.31
J4-IO31: J3.33 JM4.73 | length 35.3
  L 01 (Top) w0.2: JM4.73 77.955,11.046 78.201,10.8 79.701,9.3 102.65,9.3 103.225,8.725 103.225,6.315 103.225,3.245 J3.33
J4-IO32: J3.35 JM4.75 | length 35.9
  L 01 (Top) w0.2: JM4.75 79.225,11.026 80.561,9.69 103.66,9.69 105.725,7.625 105.725,3.285 J3.35
J4-IO33: J3.37 JM4.77 | length 36.1
  L 01 (Top) w0.2: JM4.77 80.495,11.046 81.461,10.08 104.06,10.08 108.35,5.79 108.35,3.2 J3.37
J4-IO34: J1.8 J9.1 JM4.8 | length 61.2
  L 01 (Top) w0.2: J9.1 v1(7.065,23.085) ; JM4.8 v1(36.045,19.295)
  L 02 w0.2: v1(7.065,23.085) 7.615,23.085 10.95,19.75 10.95,4.96 J1.8
  L 04 (Bot) w0.2: J1.8 10.51,7.01 12.75,9.25 33.025,9.25 35.2,11.425 35.2,15.7 36.045,16.545 v1(36.045,19.295)
J4-IO35: J1.10 J9.2 JM4.10 | length 61.7
  L 01 (Top) w0.2: J9.2 v1(7.465,24.185) ; JM4.10 v1(37.315,19.295)
  L 02 w0.2: v1(7.465,24.185) 8.015,24.185 13.05,19.15 J1.10
  L 04 (Bot) w0.2: J1.10 13.05,7.95 13.96,8.86 33.192,8.86 37.315,12.983 v1(37.315,19.295)
J4-IO36: J1.12 J9.3 JM4.12 | length 62.4
  L 01 (Top) w0.2: J9.3 v1(7.065,25.285) ; JM4.12 v1(38.585,19.295)
  L 02 w0.2: v1(7.065,25.285) 7.82,25.285 15.59,17.515 J1.12
  L 04 (Bot) w0.2: J1.12 15.59,7.765 16.295,8.47 33.445,8.47 38.585,13.61 v1(38.585,19.295)
J4-IO37: J1.14 J9.7 JM4.14 | length 65.5
  L 01 (Top) w0.2: J9.7 v1(7.065,29.685) ; JM4.14 v1(39.855,19.295)
  L 02 w0.2: v1(7.065,29.685) 7.415,29.685 7.615,29.485 7.84,29.26 18.13,18.97 J1.14
  L 04 (Bot) w0.2: J1.14 18.13,6.83 19.38,8.08 33.755,8.08 39.855,14.18 v1(39.855,19.295)
J4-IO38: J1.18 JM4.18 | length 31.2
  L 01 (Top) w0.2: JM4.18 v1(42.395,19.295)
  L 04 (Bot) w0.2: J1.18 23.21,6.71 24.19,7.69 34.09,7.69 40.25,13.85 41.275,13.85 42.395,14.97 v1(42.395,19.295)
J4-IO39: J1.20 JM4.20 | length 29.8
  L 01 (Top) w0.2: JM4.20 v1(43.665,19.295)
  L 04 (Bot) w0.2: J1.20 25.75,6.575 26.475,7.3 34.252,7.3 40.352,13.4 42.05,13.4 43.665,15.015 v1(43.665,19.295)
J4-IO40: J1.22 JM4.22 | length 28.8
  L 01 (Top) w0.2: JM4.22 v1(44.935,19.295)
  L 04 (Bot) w0.2: J1.22 28.29,6.315 28.885,6.91 34.413,6.91 40.503,13 43.525,13 44.935,14.41 v1(44.935,19.295)
J4-IO41: J1.24 JM4.24 | length 26.9
  L 01 (Top) w0.2: JM4.24 v1(46.205,19.295)
  L 04 (Bot) w0.2: J1.24 30.83,6.055 31.295,6.52 34.77,6.52 40.86,12.61 43.687,12.61 45.325,14.248 45.325,16.125 46.205,17.005 v1(46.205,19.295)
J4-IO42: J1.26 JM4.26 | length 25.2
  L 01 (Top) w0.2: JM4.26 v1(47.475,19.295)
  L 04 (Bot) w0.2: J1.26 33.37,4.764 33.689,4.764 41.145,12.22 45.045,12.22 47.475,14.65 v1(47.475,19.295)
J4-IO43: J1.28 JM4.28 | length 24.4
  L 01 (Top) w0.2: JM4.28 v1(48.745,19.295)
  L 04 (Bot) w0.2: J1.28 35.91,4.96 35.91,5.46 42.28,11.83 46.005,11.83 48.745,14.57 v1(48.745,19.295)
J4-IO44: J1.32 JM4.32 | length 21.1
  L 01 (Top) w0.2: JM4.32 v1(51.285,19.295)
  L 04 (Bot) w0.2: J1.32 40.99,4.84 46.425,10.275 51.285,15.135 v1(51.285,19.295)
J4-IO45: J1.34 JM4.34 | length 20.6
  L 01 (Top) w0.2: JM4.34 v1(52.555,19.295)
  L 04 (Bot) w0.2: J1.34 43.53,6.828 46.587,9.885 52.555,15.853 v1(52.555,19.295)
J4-IO46: J1.36 JM4.36 | length 20.1
  L 01 (Top) w0.2: JM4.36 v1(53.825,19.295)
  L 04 (Bot) w0.2: J1.36 46.07,8.395 53.825,16.15 v1(53.825,19.295)
J4-IO47: J1.38 JM4.38 | length 19.6
  L 01 (Top) w0.2: JM4.38 v1(55.095,19.295)
  L 04 (Bot) w0.2: J1.38 48.61,10.06 55.095,16.545 v1(55.095,19.295)
J4-IO48: J1.40 JM4.40 | length 19.1
  L 01 (Top) w0.2: v1(56.35,19.3) 56.36,19.3 56.365,19.295 JM4.40
  L 04 (Bot) w0.2: J1.40 51.15,11.973 56.365,17.188 56.365,19.295 56.36,19.3 v1(56.35,19.3)
J4-IO49: J3.2 JM4.42 | length 19.4
  L 01 (Top) w0.2: JM4.42 v1(57.635,19.295)
  L 04 (Bot) w0.2: v1(57.635,19.295) 57.635,17.615 63.85,11.4 J3.2
J4-IO50: J3.6 JM4.46 | length 20.5
  L 01 (Top) w0.2: JM4.46 v1(60.175,19.295)
  L 04 (Bot) w0.2: v1(60.175,19.295) 60.175,17.248 63.558,13.865 63.56,13.865 68.93,8.495 J3.6
J4-IO51: J3.8 JM4.48 | length 21
  L 01 (Top) w0.2: JM4.48 v1(61.445,19.295)
  L 04 (Bot) w0.2: v1(61.445,19.295) 61.445,16.53 63.72,14.255 63.722,14.255 71.47,6.507 J3.8
J4-IO52: J3.10 JM4.50 | length 21.5
  L 01 (Top) w0.2: JM4.50 v1(62.715,19.295)
  L 04 (Bot) w0.2: v1(62.715,19.295) 62.715,17.11 74.01,5.815 J3.10
J4-IO53: J3.12 JM4.52 | length 22.1
  L 01 (Top) w0.2: JM4.52 v1(63.985,19.295)
  L 04 (Bot) w0.2: v1(63.985,19.295) 63.985,17.085 J3.12
J4-IO54: J3.14 JM4.54 | length 22.6
  L 01 (Top) w0.2: JM4.54 v1(65.255,19.295)
  L 04 (Bot) w0.2: v1(65.255,19.295) 65.255,18.55 79.09,4.715 J3.14
J4-IO55: J3.16 JM4.56 | length 23.7
  L 01 (Top) w0.2: JM4.56 v1(66.525,19.295)
  L 04 (Bot) w0.2: v1(66.525,19.295) 66.525,18.575 78.925,6.175 79.975,6.175 J3.16
J4-IO56: J3.20 JM4.60 | length 27.1
  L 01 (Top) w0.2: JM4.60 v1(69.065,19.295)
  L 04 (Bot) w0.2: v1(69.065,19.295) 69.065,17.248 79.738,6.575 84.655,6.575 J3.20
J4-IO57: J3.22 JM4.62 | length 28.7
  L 01 (Top) w0.2: JM4.62 v1(70.335,19.295)
  L 04 (Bot) w0.2: v1(70.335,19.295) 70.335,16.53 79.9,6.965 86.805,6.965 J3.22
J4-IO58: J3.24 JM4.64 | length 29.6
  L 01 (Top) w0.2: JM4.64 v1(71.605,19.295)
  L 04 (Bot) w0.2: v1(71.605,19.295) 71.605,17.245 81.475,7.375 88.935,7.375 J3.24
J4-IO59: J3.26 JM4.66 | length 31.2
  L 01 (Top) w0.2: JM4.66 v1(72.875,19.295)
  L 04 (Bot) w0.2: v1(72.875,19.295) 72.875,16.75 81.825,7.8 91.05,7.8 J3.26
J4-IO60: J3.28 JM4.68 | length 32.6
  L 01 (Top) w0.2: JM4.68 v1(74.145,19.295)
  L 04 (Bot) w0.2: v1(74.145,19.295) 74.145,16.48 82.375,8.25 93.14,8.25 J3.28
J4-IO61: J3.30 JM4.70 | length 34.3
  L 01 (Top) w0.2: JM4.70 v1(75.415,19.295)
  L 04 (Bot) w0.2: v1(75.415,19.295) 75.415,15.762 82.537,8.64 95.29,8.64 J3.30
J5-IO01: J2.35 JM5.35 | length 20.1
  L 01 (Top) w0.2: v1(53.825,50.705) JM5.35
  L 04 (Bot) w0.2: J2.35 46.07,60.03 53.825,52.275 v1(53.825,50.705)
J5-IO02: J2.39 JM5.39 | length 19
  L 01 (Top) w0.2: v1(56.365,50.705) JM5.39
  L 04 (Bot) w0.2: J2.39 51.15,55.92 v1(56.365,50.705)
J5-IO03: J4.1 JM5.41 | length 19.4
  L 01 (Top) w0.2: v1(57.635,50.705) JM5.41
  L 04 (Bot) w0.2: v1(57.635,50.705) 57.635,59.265 J4.1
J5-IO04: J4.3 JM5.43 | length 20
  L 01 (Top) w0.2: v1(58.905,50.705) JM5.43
  L 04 (Bot) w0.2: v1(58.905,50.705) 58.905,58.035 J4.3
J5-IO05: J4.5 JM5.45 | length 20.5
  L 01 (Top) w0.2: v1(60.175,50.705) JM5.45
  L 04 (Bot) w0.2: v1(60.175,50.705) 60.175,56.725 J4.5
J5-IO06: J4.7 JM5.47 | length 21
  L 01 (Top) w0.2: v1(61.445,50.705) JM5.47
  L 04 (Bot) w0.2: v1(61.445,50.705) 61.445,55.455 J4.7
J5-IO07: J4.9 JM5.49 | length 21.8
  L 01 (Top) w0.2: v1(62.715,50.705) JM5.49
  L 04 (Bot) w0.2: v1(62.715,50.705) 62.715,54.565 73.63,65.48 J4.9
J5-IO08: J4.13 JM5.53 | length 24.4
  L 01 (Top) w0.2: v1(65.255,50.705) JM5.53
  L 04 (Bot) w0.2: v1(65.255,50.705) 65.255,54.655 74.75,64.15 77.76,64.15 J4.13
J5-IO09: J4.15 JM5.55 | length 26.6
  L 01 (Top) w0.2: v1(66.525,50.705) JM5.55
  L 04 (Bot) w0.2: v1(66.525,50.705) 66.525,54.74 75.545,63.76 81.41,63.76 81.63,63.98 J4.15
J5-IO10: J4.17 JM5.57 | length 27.6
  L 01 (Top) w0.2: v1(67.795,50.705) JM5.57
  L 04 (Bot) w0.2: v1(67.795,50.705) 67.795,54.195 76.97,63.37 81.672,63.37 83.72,63.37 84.17,63.82 J4.17
J5-IO11: J4.19 JM5.59 | length 29.2
  L 01 (Top) w0.2: v1(69.065,50.705) JM5.59
  L 04 (Bot) w0.2: v1(69.065,50.705) 69.065,54.565 77.48,62.98 85.98,62.98 86.71,63.71 J4.19
J5-IO12: J4.21 JM5.61 | length 30.4
  L 01 (Top) w0.2: v1(70.335,50.705) JM5.61
  L 04 (Bot) w0.2: v1(70.335,50.705) 70.335,54.585 78.34,62.59 86.142,62.59 86.152,62.6 88.1,62.6 89.25,63.75 J4.21
J5-IO13: J4.23 JM5.63 | length 32.1
  L 01 (Top) w0.2: v1(71.605,50.705) JM5.63
  L 04 (Bot) w0.2: v1(71.605,50.705) 71.605,54.955 78.85,62.2 90.55,62.2 91.79,63.44 J4.23
J5-IO14: J4.27 J11.5 JM5.67 | length 51.7
  L 01 (Top) w0.2: v1(74.145,50.705) JM5.67
  L 02 w0.2: J11.5 94.8,52.61 94.8,55.4 96.87,57.47 J4.27
  L 04 (Bot) w0.2: v1(74.145,50.705) 74.145,55.245 79.9,61 82.724,61 92.419,61 92.649,60.77 95.37,60.77 96.87,62.27 J4.27
J5-IO15: J4.29 J11.6 JM5.69 | length 50.5
  L 01 (Top) w0.2: v1(75.415,50.705) JM5.69
  L 02 w0.2: J11.6 99.41,56.86 J4.29
  L 04 (Bot) w0.2: v1(75.415,50.705) 75.415,55.065 80.96,60.61 82.885,60.61 92.258,60.61 92.488,60.38 98.03,60.38 99.41,61.76 J4.29
J5-IO16: J4.31 J10.5 JM5.71 | length 60.8
  L 01 (Top) w0.2: v1(76.685,50.705) JM5.71
  L 02 w0.2: J4.31 102.48,64.95 102.48,45.53 J10.5
  L 04 (Bot) w0.2: v1(76.685,50.705) 76.685,54.2 77.325,54.84 77.325,55.225 82.32,60.22 83.047,60.22 92.096,60.22 92.326,59.99 100.54,59.99 101.95,61.4 J4.31
J5-IO17: J4.33 J10.11 JM5.73 | length 53.9
  L 01 (Top) w0.2: v1(77.955,50.705) JM5.73
  L 02 w0.2: J10.11 104.08,62.73 104.49,63.14 J4.33
  L 04 (Bot) w0.2: v1(77.955,50.705) 77.955,54.705 83.08,59.83 83.208,59.83 91.934,59.83 92.164,59.6 102.85,59.6 104.49,61.24 J4.33
J5-IO18: J4.35 J10.10 JM5.75 | length 58
  L 01 (Top) w0.2: v1(79.225,50.705) JM5.75
  L 02 w0.2: J10.10 105.55,50.08 105.55,61.15 107.03,62.63 107.03,63.95 ; 107.03,64.1 107.03,63.95 ; J4.35 107.03,63.95
  L 04 (Bot) w0.2: v1(79.225,50.705) 79.225,55.025 83.64,59.44 91.773,59.44 92.003,59.21 103.41,59.21 107.03,62.83 J4.35
J5-IO19: J4.37 J10.8 JM5.77 | length 61.4
  L 01 (Top) w0.2: v1(80.495,50.705) JM5.77
  L 02 w0.2: J10.8 107.66,47.51 107.66,60.96 109.57,62.87 109.57,63.9 ; 109.57,64.12 109.57,63.9 ; J4.37 109.57,63.9
  L 04 (Bot) w0.2: v1(80.495,50.705) 80.495,55.345 84.2,59.05 91.611,59.05 91.841,58.82 104.27,58.82 109.57,64.12 J4.37
J5-IO20: J2.34 JM5.34 | length 15.8
  L 01 (Top) w0.2: J2.34 44.75,66.8 44.75,64.703 47.553,61.9 49.703,59.75 51.9,59.75 52.555,59.095 JM5.34
J5-IO21: J2.36 JM5.36 | length 14.6
  L 01 (Top) w0.2: J2.36 47.3,66.79 47.3,64.75 48.65,63.4 49.55,63.4 53.825,59.125 JM5.36
J5-IO22: J2.38 JM5.38 | length 13.5
  L 01 (Top) w0.2: J2.38 49.85,66.78 49.85,64.4 55.095,59.155 JM5.38
J5-IO23: J2.40 JM5.40 | length 13
  L 01 (Top) w0.2: J2.40 52.42,66.75 52.42,63.13 56.365,59.185 JM5.40
J5-IO24: J4.2 JM5.42 | length 16
  L 01 (Top) w0.2: JM5.42 57.635,66.185 59.25,67.8 63.63,67.8 J4.2
J5-IO25: J4.6 JM5.46 | length 17.4
  L 01 (Top) w0.2: JM5.46 60.29,57.315 60.29,62.49 62.05,64.25 67.05,64.25 67.6,64.8 67.6,66.69 J4.6
J5-IO26: J4.8 JM5.48 | length 19
  L 01 (Top) w0.2: JM5.48 61.445,62.443 62.862,63.86 69.66,63.86 70.2,64.4 70.2,66.75 J4.8
J5-IO27: J4.10 JM5.50 | length 20.2
  L 01 (Top) w0.2: JM5.50 62.715,62.565 63.62,63.47 71.72,63.47 72.8,64.55 72.8,66.81 J4.10
J5-IO28: J4.12 JM5.52 | length 21.4
  L 01 (Top) w0.2: JM5.52 63.985,62.235 64.83,63.08 73.98,63.08 75.25,64.35 75.25,66.72 J4.12
J5-IO29: J4.14 JM5.54 | length 22.4
  L 01 (Top) w0.2: JM5.54 65.255,61.855 66.09,62.69 74.142,62.69 75.402,63.95 77.4,63.95 77.75,64.3 77.75,66.68 J4.14
J5-IO30: J4.16 JM5.56 | length 23.5
  L 01 (Top) w0.2: JM5.56 66.525,61.525 67.3,62.3 74.303,62.3 75.563,63.56 79.61,63.56 80.4,64.35 80.4,66.79 J4.16
J5-IO31: J4.20 JM5.60 | length 25.9
  L 01 (Top) w0.2: JM5.60 69.065,61.165 69.81,61.91 74.465,61.91 75.725,63.17 84.37,63.17 85.45,64.25 85.45,66.76 J4.20
J5-IO32: J4.22 JM5.62 | length 27.1
  L 01 (Top) w0.2: JM5.62 70.335,60.785 71.07,61.52 74.626,61.52 75.886,62.78 86.83,62.78 88,63.95 88,66.77 J4.22
J5-IO33: J4.24 JM5.64 | length 28.3
  L 01 (Top) w0.2: JM5.64 71.605,60.505 72.23,61.13 74.788,61.13 75.908,62.25 89,62.25 90.55,63.8 90.55,66.78 J4.24
J5-IO34: J4.26 JM5.66 | length 29.4
  L 01 (Top) w0.2: JM5.66 72.875,59.825 73.79,60.74 74.949,60.74 75.909,61.7 91.35,61.7 93.15,63.5 93.15,66.84 J4.26
J5-IO35: J4.28 J11.3 JM5.68 | length 55.8
  L 01 (Top) w0.2: JM5.68 74.145,59.384 75.111,60.35 75.961,61.2 92.6,61.2 95.1,61.2 95.65,61.75 95.65,66.8 J4.28
  L 02 w0.2: J11.3 93.95,48.38 93.95,57.12 95.65,58.82 95.65,66.8 J4.28
J5-IO36: J4.30 J11.4 JM5.70 | length 54.2
  L 01 (Top) w0.2: JM5.70 75.415,59.515 76.2,60.3 76.71,60.81 92.438,60.81 96.06,60.81 98.2,62.95 98.2,66.81 J4.30
  L 02 w0.2: J11.4 100.7,53.07 100.7,66.73 J4.30
J5-IO37: J4.34 J10.7 JM5.74 | length 57.5
  L 01 (Top) w0.2: JM5.74 77.955,59.605 78.77,60.42 101.07,60.42 103.25,62.6 103.25,66.78 J4.34
  L 02 w0.2: J10.7 103,47.55 103,66.53 J4.34
J5-IO38: J4.36 J10.9 JM5.76 | length 55.2
  L 01 (Top) w0.2: JM5.76 79.225,59.275 79.98,60.03 101.58,60.03 105.75,64.2 105.75,66.74 J4.36
  L 02 w0.2: J10.9 105.15,50.08 105.15,62.55 105.75,63.15 105.75,66.74 J4.36
J5-IO39: J4.38 J10.12 JM5.78 | length 53.5
  L 01 (Top) w0.2: JM5.78 80.495,59.045 81.09,59.64 101.742,59.64 106.002,63.9 107.45,63.9 108.3,64.75 108.3,66.75 J4.38
  L 02 w0.2: J10.12 106.62,60.72 108.3,62.4 108.3,66.75 J4.38
J5-IO40: J4.40 J10.6 JM5.80 | length 63.5
  L 01 (Top) w0.2: JM5.80 81.765,58.965 82.05,59.25 101.903,59.25 105.577,62.923 109.223,62.923 110.95,64.65 110.95,66.86 J4.40
  L 02 w0.2: J10.6 108.05,45.36 108.05,60.55 110.95,63.45 110.95,66.86 J4.40
M0: J2.13 JM5.13 | length 32.8
  L 01 (Top) w0.2: v1(39.855,50.705) JM5.13
  L 04 (Bot) w0.2: J2.13 18.13,61.27 19.03,60.37 30.83,60.37 39.855,51.345 v1(39.855,50.705)
M1: J2.15 JM5.15 | length 31.9
  L 01 (Top) w0.2: v1(41.125,50.705) JM5.15
  L 04 (Bot) w0.2: J2.15 20.69,65.46 20.69,62.885 20.67,62.865 20.67,61.53 21.44,60.76 31.397,60.76 31.757,60.4 32.95,60.4 41.125,52.225 v1(41.125,50.705)
M2: J2.17 JM5.17 | length 30.1
  L 01 (Top) w0.2: v1(42.395,50.705) JM5.17
  L 04 (Bot) w0.2: J2.17 23.21,62.04 24.1,61.15 31.559,61.15 31.919,60.79 33.56,60.79 42.395,51.955 v1(42.395,50.705)
RDWR_B: J2.19 JM5.19 | length 28.5
  L 01 (Top) w0.2: v1(43.665,50.705) JM5.19
  L 04 (Bot) w0.2: J2.19 25.75,62.45 26.66,61.54 31.72,61.54 32.08,61.18 34.27,61.18 43.665,51.785 v1(43.665,50.705)
SCL: J2.5 JM5.5 | length 37.4
  L 01 (Top) w0.2: v1(34.775,50.705) JM5.5
  L 04 (Bot) w0.2: J2.5 14.25,59.2 30.345,59.2 34.775,54.77 v1(34.775,50.705)
SDA: J2.7 JM5.7 | length 36.9
  L 01 (Top) w0.2: v1(36.045,50.705) JM5.7
  L 04 (Bot) w0.2: J2.7 10.51,63.492 14.412,59.59 30.507,59.59 36.045,54.052 v1(36.045,50.705)
SPI_/C: J2.22 JM5.22 | length 24.7
  L 01 (Top) w0.2: J2.22 29.55,66.76 29.55,62.9 30.229,62.221 40.779,62.221 41.711,61.289 43.05,59.95 44.45,59.95 44.935,59.465 JM5.22
SPI_/S: J2.20 JM5.20 | length 25.9
  L 01 (Top) w0.2: J2.20 27.02,66.75 27.02,62.78 27.969,61.831 40.269,61.831 40.927,61.173 42.55,59.55 43.4,59.55 43.665,59.285 JM5.20
SPI_D: J2.12 JM5.12 | length 31
  L 01 (Top) w0.2: J2.12 16.85,66.76 16.85,62.73 19.409,60.171 37.579,60.171 38.585,59.165 JM5.12
SPI_Q: J2.18 JM5.18 | length 27.4
  L 01 (Top) w0.2: J2.18 24.45,66.78 24.45,62.15 25.159,61.441 39.859,61.441 40.554,60.746 42.15,59.15 42.395,58.905 JM5.18
SUSPEND: J2.27 JM5.27 | length 22.2
  L 01 (Top) w0.2: v1(48.745,50.705) JM5.27
  L 04 (Bot) w0.2: J2.27 35.91,64.19 48.745,51.355 v1(48.745,50.705)
TCK: J3.38 J6.6 J7.4 JM4.78 | length 61.1
  L 01 (Top) w0.2: JM4.78 v1(80.495,19.295) ; J6.6 105,19.4 104.27,18.67 J7.4 104.27,12.755 109.57,7.455 J3.38
  L 04 (Bot) w0.2: v1(80.495,19.295) 80.495,13.312 83.307,10.5 103.59,10.5 J3.38
TDI: J3.34 J6.10 J7.2 JM4.74 | length 78.8
  L 01 (Top) w0.2: JM4.74 v1(77.955,19.295) ; J7.2 99.19,18.09 101,19.9 J6.10
  L 04 (Bot) w0.2: v1(77.955,19.295) 77.955,14.749 82.984,9.72 101.23,9.72 104.49,6.46 J3.34 105.99,3.02 113.57,3.02 113.95,3.4 113.95,5.85 113.16,6.64 111.16,6.64 103,14.8 103,17.45 102.375,18.075 100.065,18.075 J7.2
TDO: J3.36 J6.8 J7.3 JM4.76 | length 71.4
  L 01 (Top) w0.2: JM4.76 v1(79.225,19.295) ; J7.3 101.73,18.13 103,19.4 J6.8
  L 04 (Bot) w0.2: v1(79.225,19.295) 79.225,14.03 83.145,10.11 101.44,10.11 J3.36 108.14,3.41 113.21,3.41 113.56,3.76 113.56,5.49 112.8,6.25 110.775,6.25 101.73,15.295 J7.3
TMS: J3.40 J6.4 J7.1 JM4.80 | length 70.8
  L 01 (Top) w0.2: JM4.80 v1(81.765,19.295) ; J7.1 96.65,18.975 95.725,19.9 95.725,24.55 96.075,24.9 106.5,24.9 107,24.4 J6.4
  L 04 (Bot) w0.2: v1(81.765,19.295) 81.765,16.31 81.075,15.62 81.075,13.284 83.469,10.89 104.86,10.89 111.23,4.52 J3.40 ; 96.65,10.915 J7.1
VCCAUX: C9.1 C21.1 J3.32 J6.2 J7.6 JM4.72 | length 80.8
  L 01 (Top) w0.3: JM4.72 v1(76.685,19.295) 76.685,20.335 C21.1 ; J3.32 C9.1
  L 01 (Top) w0.5: J6.2 109,17.55 J7.6
  L 04 (Bot) w0.5: J3.32 97.29,9.18 82.76,9.18 76.685,15.255 v1(76.685,19.295) 80.115,22.725 103.825,22.725 J7.6
VCCCIO0: C5.1 C7.1 C15.1 C17.1 J1.30 J3.4 JM4.30 JM4.44 | length 62.3
  L 01 (Top) w0.2: C7.1@66.39,6.64 C7.1
  L 01 (Top) w0.3: C5.1@37.85,6.5 37.85,5.12 J1.30 ; C15.1 51.12,20.4 ; JM4.30 v1(50.015,19.295) C15.1@50.015,20.385 ; 57.675,20.875 58.15,20.4 C17.1 58.905,20.395 v1(58.905,19.295) JM4.44 ; J3.4 C7.1@66.39,6.64
  L 01 (Top) w1: 51.12,20.4 53.72,23 57,23 57.675,22.325 57.675,20.875
  L 04 (Bot) w0.5: J1.30 38.45,6.7 42.825,11.075 46.275,11.075 50.015,14.815 v1(50.015,19.295) ; v1(58.905,19.295) 58.905,17.395 66.39,9.91 J3.4
VREF0: C6.1 C16.1 J1.37 JM4.37 | length 24.8
  L 01 (Top) w0.2: J1.37 49.88,3.25 52.9,3.25 54.1,4.45 C6.1 54.21,5.45 55.095,6.335 JM4.37 ; v1@55.095,14.645 v1(55.25,14.8)
  L 01 (Top) w0.3: JM4.37 v1@55.095,14.645 ; C16.1 56.658,20.4 56.75,20.308 v1(56.75,20.3)
  L 04 (Bot) w0.2: v1(55.25,14.8) 56.995,16.545 56.995,20.155 56.849,20.301 v1@56.751,20.301
pads on no net: J6.12 J6.14 J8.2 JM4.H1 JM4.H2 JM5.H1 JM5.H2 PM1.0 PM2.0 PM3.0
copper on no net: | length 88
  L 01 (Top) w0.15: 103.575,32.35 112.575,32.35 112.575,34.35 103.575,34.35 103.575,32.35
  L 02 w0.15: 103.575,32.35 103.575,34.35 112.575,34.35 112.575,32.35 103.575,32.35
  L 03 w0.15: 103.575,32.35 103.575,34.35 112.575,34.35 112.575,32.35 103.575,32.35
  L 04 (Bot) w0.15: 103.575,32.35 112.575,32.35 112.575,34.35 103.575,34.35 103.575,32.35

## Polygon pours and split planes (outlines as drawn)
5VB2B on L 02 "Bottom Layer-No Net" (solid, remove dead copper, pour order 1001): -1,32 17,32 21,36 34,49 34,52 34,58 33,58 29,58 14,58 13,59 7,65 7,66 7,70 6,71 -1,71
3.3V on L 02 "Bottom Layer-No Net" (solid, remove dead copper, pour order 1000): 0,31 18,31 32,45 35,48 35,53 35,59 16,59 14,59 10,63 8,65 8,70 115,70 115,0 0,0
GND on L 03 "Bottom Layer-No Net" (solid, remove dead copper, pour order 1000): 0,0 0.259,-0.259 115,-0.259 115,70 0,70

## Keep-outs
Keep-Out Layer:
  the board outline again, w0.3

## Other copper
L 01 (Top):
  text "L1" at 104.075,32.85 h1
L 02:
  text "L2" at 106.075,32.85 h1
L 03:
  text "L3" at 108.075,32.85 h1
L 04 (Bot):
  text "L4" at 112.075,32.85 h1

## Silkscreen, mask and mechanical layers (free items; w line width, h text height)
Boardumrandung:
  the board outline again, w0.01
Beschriftung:
  text "2" at 61.1,67.5 h1.5
  text "1" at 0.7,64.8 h1.5
  text "1" at 63.6,62.1 h1.5
  text "J2" at 24.568,62.032 h1.5
  text "J4" at 87.9,61.7 h1.5
  text "2" at 31.8,59.5 h1.5
  text "J11" at 98.425,55.245 h1.5
  text "1" at 32.1,48.5 h1.5
  text "JM5" at 54.2,48 h1.5
  text "J8" at 17.25,46.6 h1.5
  text "Center +" at 14.95,43.5 h1.5
  text "GND" at 9.5,42.1 h1.5
  text "1" at 98.552,40.132 h1.5
  text "J5" at 9.25,39.4 h1.5
  text "1" at 106.807,36.449 h1.5
  text "J10" at 109.855,35.56 h1.5
  text "S1" at 100.203,34.798 h1.5
  text "Reset" at 100.203,32.766 h1.5
  text "+5V" at 8.3,32.6 h1.5
  text "J6" at 106.8,30.5 h1.5
  text "www.trenz-electronic.de" at 42,30 h1.5
  text "1" at 110.6,29.7 h1.5
  text "TE0323-00 / 2009" at 46.5,27 h1.5
  text "JM4" at 62.8,20.6 h1.5
  text "2" at 31.8,19.3 h1.5
  text "VREF" at 108.5,18.7 h1.5
  text "1" at 94.1,16.2 h1.5
  text "J7" at 111.3,15.9 h1.5
  text "J9" at 14.05,15.85 h1.5
  text "TMS" at 95.9,14.8 h1.5 r270
  text "TDI" at 98.5,14.8 h1.5 r270
  text "TDO" at 101.1,14.8 h1.5 r270
  text "TCK" at 103.5,14.8 h1.5 r270
  text "GND" at 106.1,14.8 h1.5 r270
  text "1" at 32,8.9 h1.5
  text "J1" at 25.2,7.1 h1.5
  text "J3" at 86.9,7.1 h1.5
  text "2" at 60.7,3.8 h1.5
  text "1" at 0.5,1.2 h1.5
  text "1" at 60.9,1.1 h1.5
Mechanical 13:
  lines w0.3: 21.449,19.801 21.449,31.101 22.975,31.101 22.999,31.125 22.999,59.001 90.999,59.001 90.999,11.001 22.999,11.001 22.999,19.775 22.974,19.801 21.449,19.801
  text "PMOD" at 92.15,55.7 h1
  text "1" at 92.456,52.705 h1.5
  text "PMOD" at 101.6,52.705 h1
  text "1" at 101.981,50.8 h1.5
  text "2" at 92.202,50.165 h1.5
  text "2" at 101.727,48.26 h1.5
  text "3" at 92.202,47.625 h1.5
  text "3" at 101.727,45.72 h1.5
  text "4" at 92.202,45.085 h1.5
  text "4" at 101.727,43.18 h1.5
  text "5" at 92.202,42.545 h1.5
  text "5" at 101.727,40.64 h1.5
  text "6" at 92.202,40.005 h1.5
  text "6" at 101.727,38.1 h1.5

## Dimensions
0,0 to 2.89,59.13 on Dimension
0,0 to 2.89,10.87 on Dimension
112.11,10.87 to 112.11,59.13 on Dimension
115,0 to 115,70 on Dimension
0,70 to 112.11,59.13 on Dimension
0,70 to 2.89,59.13 on Dimension
2.89,10.87 to 112.11,10.87 on Dimension
0,0 to 115,0 on Dimension
0,0 to 2.89,1.98 on Dimension1
0,70.254 to 2.89,65.48 on Dimension1
0,70 to 63.85,65.48 on Dimension1
0,70 to 2.89,65.48 on Dimension1
0,-0.254 to 63.85,1.98 on Dimension1
0,0 to 2.89,1.98 on Dimension1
